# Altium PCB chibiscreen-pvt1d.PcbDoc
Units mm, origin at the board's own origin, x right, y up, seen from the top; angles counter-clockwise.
Board outline 47.28 x 42.63 mm, 2 copper layers (Top Layer, Bottom Layer), stack 1.571 mm thick; 38 components, 30 nets, 404 pads, 49 vias.
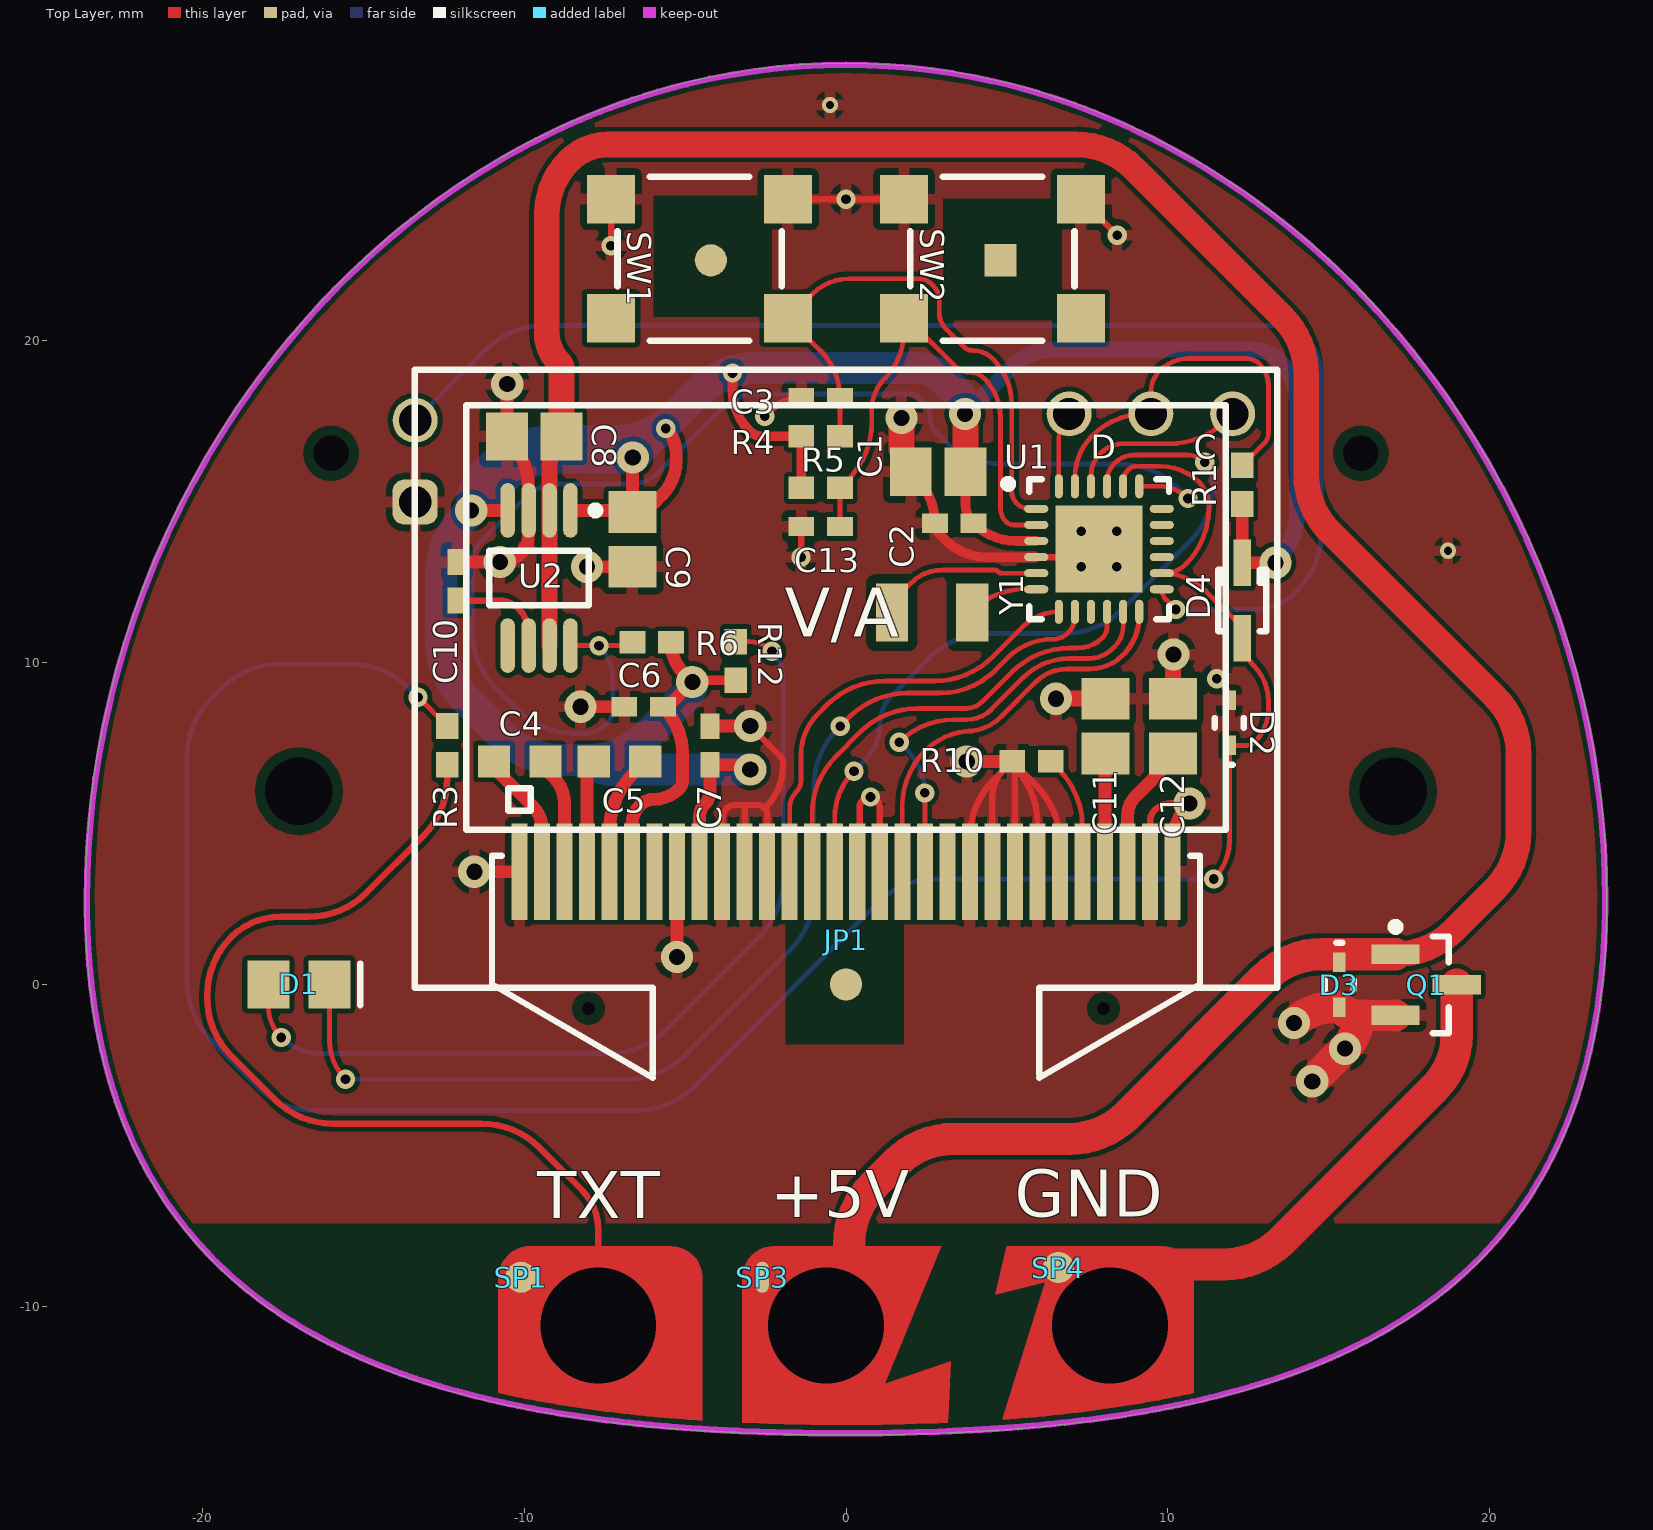
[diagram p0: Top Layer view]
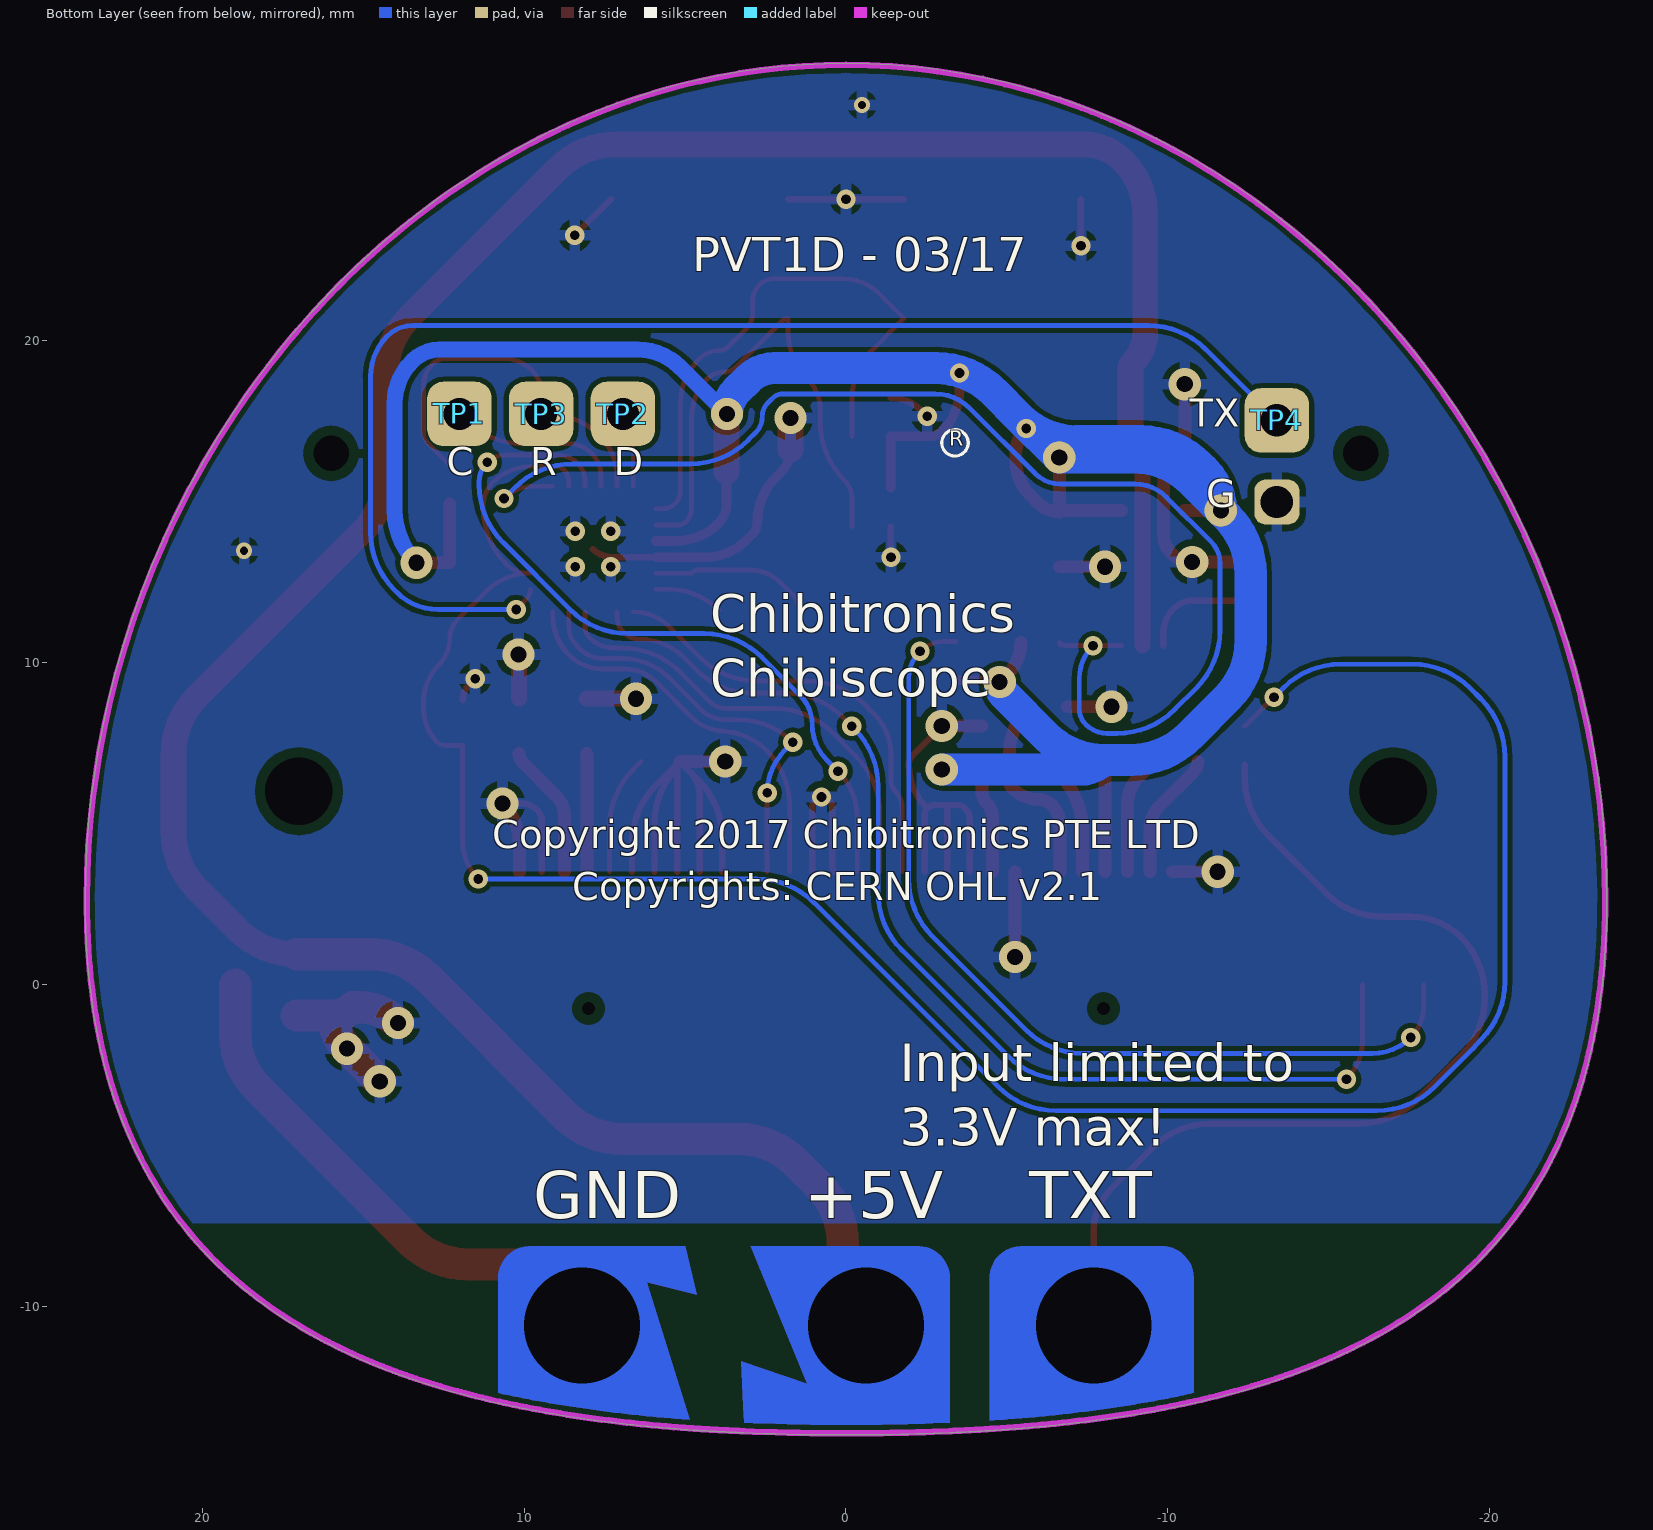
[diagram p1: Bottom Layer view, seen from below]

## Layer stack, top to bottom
Top Solder: solder mask 0.0102, Solder Resist, Dk 3.5
Top Layer: signal copper 0.0356
Dielectric 1: dielectric 1.5, FR-4, Dk 4.8
Bottom Layer: signal copper 0.0356
Bottom Solder: solder mask 0.0102, Solder Resist, Dk 3.5

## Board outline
1747 vertices, not listed, extent -23.641,-14 23.641,28.625

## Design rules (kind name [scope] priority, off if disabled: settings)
Clearance Clearance_NPTH [PadIsPlated = 'False'] p1: gap=0.3 ignorepadtopadclearanceinfootprint=FALSE except(0: Arc-Hole Track-Hole SMDPad-Hole THPad-Hole Via-Hole Fill-Hole Poly-Hole Region-Hole Text-Hole)
Clearance [All] p2: gap=0.15 ignorepadtopadclearanceinfootprint=FALSE except(0: Arc-Hole Track-Hole SMDPad-Hole THPad-Hole Via-Hole Fill-Hole Poly-Hole Region-Hole Text-Hole)
ComponentClearance [All] p1 off: gap=0.254 collisioncheckmode=3 verticalgap=0.254 showdistances=FALSE
HoleSize [All] p1: absolutevalues=TRUE maxlimit=4 minlimit=0.025 maxpercent=80.000 minpercent=20.000
MinimumSolderMaskSliver [All] p1 off: minsoldermaskwidth=0.254
NetAntennae [All] p1 off: netantennaetolerance=0
PlaneConnect [All] p1: planeconnectstyle=Relief reliefexpansion=0.4 reliefentries=4 reliefconductorwidth=0.35 reliefairgap=0.2
PolygonConnect [All] p1: connectstyle=Relief reliefconductorwidth=0.35 reliefentries=4 polygonreliefangle="90 Angle" airgapwidth=0.2
RoomDefinition 01oled [InComponentClass('01oled')] p1 off: confinementstyle=ConfineIn formatcopy=TRUE lockcomponents=FALSE outline 70.294,-25.539 62.928,-25.539 62.928,-29.476 70.294,-29.476
RoutingVias [All] p1: holewidth=0.3 width=0.6 viastyle="Through Hole" minholewidth=0.3 minwidth=0.6 maxholewidth=0.8 maxwidth=1.2
SilkToSilkClearance [All] p1 off: silktosilkclearance=0.254
SilkToSolderMaskClearance [IsPad] p1 off: minsilkscreentomaskgap=0.254 clearancetoexposedcopper=TRUE
SolderMaskExpansion [All] p1: expansion=0.08
Width [All] p1: maxlimit=1 minlimit=0.15 preferedwidth=0.2
23 further rules are at their usual default settings.

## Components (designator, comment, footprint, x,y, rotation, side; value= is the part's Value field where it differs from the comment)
C1 "10uF, 10V, X5R" CAPC2012N 2.863,15.928 r180 top
C2 "0.1uF, 10V, X5R" CAPC1005N 3.363,14.328 r180 top
C3 "0.01uF, 10V, X7R" CAPC1005N -0.787,18.228 r180 top
C4 "1.0uF, 25V, X5R" CAPC1608N -10.137,6.928 r180 top
C5 "1.0uF, 25V, X5R" CAPC1608N -7.037,6.928 r180 top
C6 "1.0uF, 10V, X5R" CAPC1005N -6.287,8.628 r180 top
C7 "1.0uF, 10V, X5R" CAPC1005N -4.225,7.425 r90 top
C8 "10uF, 10V, X5R" CAPC2012N -9.687,17.028 r180 top
C9 "10uF, 10V, X5R" CAPC2012N -6.637,13.828 r270 top
C10 "0.033uF, 16V, X7R" CAPC1005N -12.087,12.528 r270 top
C11 "4.7uF, 25V, X7R" CAPC2012N 8.063,8.028 r90 top
C12 "4.7uF, 25V, X7R" CAPC2012N 10.163,8.028 r90 top
C13 "0.01uF, 10V, X7R" CAPC1005N -0.787,14.228 r180 top
D1 "white LED 0805" CD2012-0805 -17,0 r0 top
D2 "ESD5Z3.3T1" SOD-523 11.913,8.128 r90 top
D3 "ESD5Z5.0T1G" SOD-523 15.328,-0.013 r270 top
D4 "NSR0530HT1G" SOD-323 12.313,11.928 r90 top
JP1 "ER-OLED0.96-3W" ER-OLED0.96-FOLD 0,4 r0 top locked
Q1 "AO3414" SOT23-3N 18.028,-0.013 r0 top
R1 "10k, 1%" RESC1005N 12.313,15.528 r90 top
R3 "330, 1%" RESC1005N -12.387,7.428 r90 top
R4 "1k, 1%" RESC1005N -0.787,17.028 r0 top
R5 "1k, 1%" RESC1005N -0.787,15.428 r0 top
R6 "10k, 1%" RESC1005N -6.037,10.628 r180 top
R10 "390k, 1%" RESC1005N 5.763,6.928 r180 top
R12 "330, 1%" RESC1005N -3.425,10.05 r90 top
SP1 "sticker pad (DNP)" TP_SMT_38mil#1 -10.1,-9.1 r90 top
SP3 "sticker pad (DNP)" TP_SMT_38mil#2 -2.6,-9.1 r90 top
SP4 "sticker pad (DNP)" TP_SMT_38mil#1 6.6,-8.8 r90 top
SW1 "5x5mm 1.6mm tall PB" SWITCH_TS-1187A -1.8,24.4 r270 top
SW2 "5x5mm 1.6mm tall PB" SWITCH_TS-1187A 7.3,24.4 r270 top
TP1 "test point (DNP)" TP_2MM_SQ 12.013,17.728 r180 bottom
TP2 "test point (DNP)" TP_2MM_SQ 6.933,17.728 r180 bottom
TP3 "test point (DNP)" TP_2MM_SQ 9.473,17.728 r180 bottom
TP4 "test point (DNP)" TP_2MM_SQ -13.387,17.528 r180 bottom
U1 "MKL02Z32VFK4" QFN50P400X400X100_HS-25N 7.863,13.528 r0 top
U2 "LP3982IMM-3.3/NOPB" MUA08A_N -9.537,12.628 r270 top
Y1 "32.768kHz" ABS07-120 2.675,11.55 r0 top

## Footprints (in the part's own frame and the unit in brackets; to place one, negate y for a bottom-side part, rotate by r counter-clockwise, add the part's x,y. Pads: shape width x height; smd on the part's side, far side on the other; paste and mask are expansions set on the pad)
ABS07-120 [mm] "32.768kHz SMD low-ESR"
  rect 1x1.8 smd: 1(-1.25,0) 2(1.25,0)
  body extent -1.6,-0.75 1.6,0.75, height 0.9
CAPC1005N [mm] "Chip Capacitor, Body 1.0x0.5mm, IPC Medium Density"
  rect 0.8x0.6 smd: 1(-0.6,0) 2(0.6,0)
  body extent -0.55,-0.3 0.55,0.3, height 0.6
CAPC1608N [mm] "Chip Capacitor, Body 1.6x0.8mm, IPC Medium Density"
  rect 1x1 smd: 1(-0.8,0) 2(0.8,0)
  body extent -0.88,-0.48 0.87,0.48, height 0.85
CAPC2012N [mm] "Chip Capacitor, Body 2.0x1.3mm, IPC Medium Density"
  rect 1.3x1.5 smd: 1(-0.85,0) 2(0.85,0)
  body extent -1.1,-0.72 1.1,0.73, height 1.1
CD2012-0805 [mm] "Chip Diode; Body 2.0 x 1.3 mm (LxW typ)"
  rect 1.3x1.5 smd: 1(-0.95,0) 2(0.95,0)
  silkscreen extent 1.9,-0.65 1.9,0.65
ER-OLED0.96-FOLD [mm] "ER-OLED 0.96in Direct to PCB mount, folded"
  round 0.2 hole 0.4 unplated mask+0.3: 0(8,-4.75) 1(-8,-4.75)
  rect 0.5x3 smd mask+0.07: 1(-10.15,-0.5) 2(-9.45,-0.5) 3(-8.75,-0.5) 4(-8.05,-0.5) 5(-7.35,-0.5) 6(-6.65,-0.5) 7(-5.95,-0.5) 8(-5.25,-0.5) 9(-4.55,-0.5) 10(-3.85,-0.5) 11(-3.15,-0.5) 12(-2.45,-0.5) 13(-1.75,-0.5) 14(-1.05,-0.5) 15(-0.35,-0.5) 16(0.35,-0.5) 17(1.05,-0.5) 18(1.75,-0.5) 19(2.45,-0.5) 20(3.15,-0.5) 21(3.85,-0.5) 22(4.55,-0.5) 23(5.25,-0.5) 24(5.95,-0.5) 25(6.65,-0.5) 26(7.35,-0.5) 27(8.05,-0.5) 28(8.75,-0.5) 29(9.45,-0.5) 30(10.15,-0.5)
  silkscreen extent -13.4,-6.9 13.4,15.1, body extent -13.4,-4.1 13.4,15.1, height 1.61
MUA08A_N [mm] "TSOP, 8-Leads, Body 3x3mm, Pitch 0.65mm, IPC Medium Density"
  oval 1.7x0.45 smd: 1(-2.1,0.975) 2(-2.1,0.325) 3(-2.1,-0.325) 4(-2.1,-0.975) 5(2.1,-0.975) 6(2.1,-0.325) 7(2.1,0.325) 8(2.1,0.975)
  silkscreen extent -2.22,-1.55 0.85,1.88, body extent -1.55,-1.55 1.55,1.55, height 1.09
QFN50P400X400X100_HS-25N [mm] "QFN, 24-Leads, Body 4.00x4.00mm, Pitch 0.50mm, Thermal Pad 2.80x2.80mm, IPC Medium Density"
  oval 0.75x0.25 smd mask+0.07: 1(-1.95,1.25) 2(-1.95,0.75) 3(-1.95,0.25) 4(-1.95,-0.25) 5(-1.95,-0.75) 6(-1.95,-1.25) 13(1.95,-1.25) 14(1.95,-0.75) 15(1.95,-0.25) 16(1.95,0.25) 17(1.95,0.75) 18(1.95,1.25)
  oval 0.25x0.75 smd mask+0.07: 7(-1.25,-1.95) 8(-0.75,-1.95) 9(-0.25,-1.95) 10(0.25,-1.95) 11(0.75,-1.95) 12(1.25,-1.95) 19(1.25,1.95) 20(0.75,1.95) 21(0.25,1.95) 22(-0.25,1.95) 23(-0.75,1.95) 24(-1.25,1.95)
  rect 2.7x2.7 smd mask+0: 25(0,0)
  silkscreen extent -2.95,-2.17 2.18,2.18, body extent -2.03,-2.03 2.03,2.03, height 1
RESC1005N [mm] "Chip Resistor, Body 1.1x0.5mm, IPC Medium Density"
  rect 0.8x0.7 smd: 1(-0.6,0) 2(0.6,0)
  body extent -0.55,-0.3 0.55,0.3, height 0.4
SOD-323 [mm] "SOD-323/SC-76; 2 Leads; Body 1.7 x 1.3 mm, (LxW)"
  rect 1.45x0.55 smd: 1(1.175,0) 2(-1.175,0)
  silkscreen extent -0.95,-0.75 0.95,0.75
SOD-523 [mm] "Molded Diode, 2-Leads, Body 1.2x0.8mm, IPC Medium Density"
  rect 0.6x0.4 smd: 1(-0.7,0) 2(0.7,0)
  silkscreen extent -1.3,-0.45 0.15,0.45, body extent -0.65,-0.45 0.65,0.45, height 0.7
SOT23-3N [mm] "SOT23, 3-Leads, Body 2.9x1.3mm, Pitch 0.95mm, Lead Span 2.5mm, IPC Medium Density"
  rect 1.5x0.6 smd: 1(-0.95,0.95) 2(-0.95,-0.95) 3(0.95,0)
  silkscreen extent -1.07,-1.5 0.7,1.92, body extent -0.7,-1.5 0.7,1.5, height 1.1
SWITCH_TS-1187A [mm] "TS-1187A tact switch, Chi Fung Electronics"
  rect 1.5x1.5 smd mask+0.07: 1(0,0) 2(0,-5.5) 3(3.7,0) 4(3.7,-5.5)
  silkscreen extent -0.7,-5.3 4.4,-0.2, body extent -0.7,-5.3 4.4,-0.2, height 1.6
TP_2MM_SQ [mm] "2mm x 2mm square test pad"
  rrect50% 2x2 smd: 1(0,0)
TP_SMT_38mil#1 [mil] "38 mil round test point, SMT"
  round 38 smd: 1(0,0)
TP_SMT_38mil#2 [mil] "38 mil round test point, SMT"
  oval 38x15.75 smd: 1(0,0)

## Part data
C1 C8 C9: library part "Cap Semi", "Capacitor (Semiconductor SIM Model)", MPN=CL21A106KPCLQNC
C2: library part "Cap Semi", "Capacitor (Semiconductor SIM Model)", MPN=CL05A104KP5NNNC
C3 C13: library part "Cap Semi", "Capacitor (Semiconductor SIM Model)", MPN=CL05B103KP5NNNC
C4 C5: library part "Cap Semi", "Capacitor (Semiconductor SIM Model)", MPN=CL10A105KA8NNNC
C6 C7: library part "Cap Semi", "Capacitor (Semiconductor SIM Model)", MPN=CL05A105KP5NNND
C10: library part "Cap Semi", "Capacitor (Semiconductor SIM Model)", MPN=CL05B333KO5NNNC
C11 C12: library part "Cap Semi", "Capacitor (Semiconductor SIM Model)", MPN=CL21B475KAFNNNE
D1: library part LED2, "White LED", MPN=CB-2012QWC-P8
D2: library part Tranzorb, "On Semi 3.3V standoff TVS diode", MPN=ESD5Z3.3T1G
D3: library part Tranzorb, "On Semi 5.0V standoff TVS diode"
D4: library part "D Schottky", "Schottky Diode", MPN=NSR0530H-D
JP1: "0.96in OLED, 128x64, white"
Q1: library part MOSFET-N, "N-Channel MOSFET"
R1 R6: library part Res1, "Resistor", MPN=RS02U103FT
R3: library part Res1, "Resistor", MPN=RS02U101FT
R4 R5: library part Res1, "Resistor", MPN=RS02U102FT
R10: library part Res1, "Resistor", MPN=RS02U394FT
R12: library part Res1, "Resistor", MPN=RS02U331FT
SP1 SP3 SP4 TP1 TP2 TP3 TP4: library part CON1, "Connector"
SW1 SW2: library part "Header 4", "Chi Fung TS-1187A", MPN=SW-PB-5X5-1.6
U1: "Kinetis KL02 32 KB Flash, 48MHz Cortex-M0+"
U2: "Micropower, Ultra Low-Dropout, Low-Noise, 300mA CMOS Regulator, 8-pin Mini SOIC, Pb-Free", Manufacturer="National Semiconductor", PackageTopMarking=ZXTT*LEUB, PowerWise=N
Y1: library part XTAL, "3.2 x 1.5mm 32.768 kHz crystal, 6pF CL 70k ESR, 20ppm", MPN=SJFC1332K06F20

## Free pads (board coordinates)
  round 2 hole 2.1 unplated: 0(-17,6) 0(17,6)
  round 0.7 hole 1.1 unplated: 0(-16,16.5) 0(16,16.5)
  round 1.8 hole 3.6 mask+0.07: 0(-7.7,-10.6) 0(-0.625,-10.6) 0(8.2,-10.6)
  rect 0.254x0.051 on Bottom Overlay: 1(-2.553,13.231) 1(-2.553,13.282) 1(-2.553,13.333) 1(-2.553,13.383) 1(-2.553,13.434) 1(-2.553,13.485) 1(-2.553,13.536) 1(-2.553,13.587) 1(-2.553,13.637) 1(-2.553,13.688) 1(-2.553,13.739) 1(-2.553,13.79) 1(-2.553,13.841) 1(-2.553,13.891) 1(-2.553,13.993) 1(-2.553,14.044) 1(-2.553,14.095) 1(-2.553,14.145) 1(-2.553,14.196) 1(-2.553,14.247) 1(-2.553,14.349) 1(-2.553,14.399) 1(-2.553,14.45) 1(-2.553,14.501) 1(-2.553,14.552) 1(-2.553,14.603) 1(-2.553,14.653) 1(-2.553,14.755) 1(-2.553,14.806) 1(-2.553,14.857) 1(-2.553,14.907) 1(-2.553,14.958) 1(-2.553,15.009) 1(-2.553,15.111) 1(-2.553,15.161) 1(-2.553,15.212) 1(-2.553,15.263) 1(-2.553,15.314) 1(-2.553,15.365) 1(-2.553,15.466) 1(-2.553,15.517) 1(-2.553,15.568) 1(-2.553,15.619) 1(-2.553,15.669) 1(-2.553,13.18) 1(-2.553,13.942) 1(-2.553,14.298) 1(-2.553,14.704) 1(-2.553,15.06) 1(-2.553,15.415) 1(-2.502,12.977) 1(-2.502,13.028) 1(-2.502,15.822) 1(-2.451,15.974) 1(-0.724,13.079) 1(0.749,13.079) 1(2.426,16.025) 1(2.476,15.923) 1(2.476,12.926) 1(2.527,13.079) 1(2.527,13.129) 1(2.527,15.72) 1(2.527,15.771) 1(2.578,13.282) 1(2.578,13.333) 1(2.578,13.383) 1(2.578,13.434) 1(2.578,13.485) 1(2.578,13.536) 1(2.578,13.587) 1(2.578,13.637) 1(2.578,13.688) 1(2.578,13.739) 1(2.578,13.79) 1(2.578,13.841) 1(2.578,13.891) 1(2.578,13.942) 1(2.578,13.993) 1(2.578,14.044) 1(2.578,14.095) 1(2.578,14.145) 1(2.578,14.196) 1(2.578,14.247) 1(2.578,14.298) 1(2.578,14.349) 1(2.578,14.399) 1(2.578,14.45) 1(2.578,14.501) 1(2.578,14.552) 1(2.578,14.603) 1(2.578,14.653) 1(2.578,14.704) 1(2.578,14.755) 1(2.578,14.806) 1(2.578,14.857) 1(2.578,14.907) 1(2.578,14.958) 1(2.578,15.009) 1(2.578,15.06) 1(2.578,15.111) 1(2.578,15.161) 1(2.578,15.212) 1(2.578,15.263) 1(2.578,15.314) 1(2.578,15.365) 1(2.578,15.415) 1(2.578,15.466) 1(2.578,15.517)
  rect 0.305x0.051 on Bottom Overlay: 1(-2.527,13.079) 1(-2.527,13.129) 1(-2.527,15.72) 1(-2.527,15.771) 1(-2.477,12.875) 1(-2.477,12.926) 1(-2.477,15.873) 1(-2.477,15.923) 1(-2.426,12.774) 1(-2.426,12.825) 1(-2.426,16.025) 1(-2.426,16.076) 1(-2.375,12.672) 1(-2.375,12.723) 1(-2.375,16.127) 1(-2.324,12.621) 1(-2.324,16.228) 1(-2.273,12.52) 1(-2.273,16.279) 1(-2.223,12.469) 1(-0.749,13.028) 1(-0.699,12.926) 1(-0.699,12.977) 1(0.013,12.977) 1(0.013,13.028) 1(0.013,13.079) 1(0.724,12.977) 1(0.724,13.028) 1(1.283,13.637) 1(1.283,13.688) 1(1.283,14.399) 1(1.283,14.45) 1(1.283,13.485) 1(1.283,13.536) 1(1.283,13.587) 1(1.283,13.739) 1(1.283,13.79) 1(1.283,13.841) 1(1.283,13.891) 1(1.283,14.247) 1(1.283,14.298) 1(1.283,14.349) 1(1.283,14.501) 1(1.283,14.552) 1(1.283,14.603) 1(1.283,14.653) 1(2.248,16.33) 1(2.299,12.571) 1(2.299,16.279) 1(2.349,12.621) 1(2.349,12.672) 1(2.349,16.177) 1(2.4,12.723) 1(2.4,12.774) 1(2.4,16.076) 1(2.4,16.127) 1(2.451,15.974) 1(2.451,12.825) 1(2.451,12.875) 1(2.502,15.822) 1(2.502,12.977) 1(2.502,13.028) 1(2.502,15.873) 1(2.553,13.18) 1(2.553,13.231) 1(2.553,15.568) 1(2.553,15.619) 1(2.553,15.669)
  rect 0.356x0.051 on Bottom Overlay: 1(-2.35,16.177) 1(-2.299,12.571) 1(-2.248,16.33) 1(-2.197,16.381) 1(-2.197,12.418) 1(-2.146,12.367) 1(-2.146,16.431) 1(-2.096,12.317) 1(0.648,12.875) 1(0.698,12.926) 1(2.07,16.533) 1(2.121,12.367) 1(2.121,16.482) 1(2.172,12.418) 1(2.172,16.431) 1(2.222,12.469) 1(2.222,16.381) 1(2.273,12.52) 1(2.324,16.228)
  rect 0.406x0.051 on Bottom Overlay: 1(-2.121,16.482) 1(-2.07,16.533) 1(-2.019,16.584) 1(-2.019,12.266) 1(-1.969,12.215) 1(-0.648,12.875) 1(0.013,12.926) 1(1.943,16.635) 1(1.994,16.584) 1(2.045,12.266) 1(2.095,12.317)
  rect 0.457x0.051 on Bottom Overlay: 1(-1.943,16.635) 1(-1.892,12.164) 1(-0.368,12.621) 1(1.867,16.685) 1(1.918,12.164) 1(1.968,12.215)
  rect 0.508x0.051 on Bottom Overlay: 1(-1.867,16.685) 1(-1.816,12.113) 1(-1.765,16.736) 1(0.013,12.875) 1(0.368,12.621) 1(1.791,16.736) 1(1.841,12.113)
  rect 0.559x0.051 on Bottom Overlay: 1(-1.74,12.063) 1(1.714,12.063)
  rect 0.61x0.051 on Bottom Overlay: 1(-1.664,16.787) 1(0.368,12.672) 1(1.689,16.787)
  rect 0.66x0.051 on Bottom Overlay: 1(-1.588,12.012) 1(-0.368,12.672) 1(1.613,12.012)
  rect 0.762x0.051 on Bottom Overlay: 1(-1.537,16.838) 1(1.511,16.838)
  rect 1.27x0.051 on Bottom Overlay: 1(-1.283,13.942) 1(-1.283,13.993) 1(-1.283,14.095) 1(-1.283,14.196) 1(-1.283,14.044) 1(-1.283,14.145) 1(1.308,14.044) 1(1.308,14.095) 1(1.308,14.145) 1(1.308,13.993)
  rect 0.152x0.051 on Bottom Overlay: 1(-0.368,12.571)
  rect 1.473x0.051 on Bottom Overlay: 1(-0.013,12.723)
  rect 1.575x0.051 on Bottom Overlay: 1(-0.013,12.774)
  rect 3.099x0.051 on Bottom Overlay: 1(-0.013,11.809)
  rect 3.708x0.051 on Bottom Overlay: 1(-0.013,11.961)
  rect 3.2x0.051 on Bottom Overlay: 1(-0.013,16.99)
  rect 2.743x0.051 on Bottom Overlay: 1(0.013,11.758)
  rect 3.353x0.051 on Bottom Overlay: 1(0.013,11.859)
  rect 3.556x0.051 on Bottom Overlay: 1(0.013,11.91)
  rect 1.626x0.051 on Bottom Overlay: 1(0.013,12.825)
  rect 3.658x0.051 on Bottom Overlay: 1(0.013,16.889)
  rect 3.454x0.051 on Bottom Overlay: 1(0.013,16.939)
  rect 2.946x0.051 on Bottom Overlay: 1(0.013,17.041)
  rect 2.54x0.051 on Bottom Overlay: 1(0.013,17.092)
  rect 0.203x0.051 on Bottom Overlay: 1(0.368,12.571)
  rect 1.219x0.051 on Bottom Overlay: 1(1.283,13.942) 1(1.283,14.196)
  rrect50% 1.4x1.4 hole 1: 4(-13.387,14.988)
  round 1.4 hole 1: 4(-13.387,17.528) 4(6.933,17.728) 4(9.473,17.728) 4(12.013,17.728)
  round 1 smd mask+1: 6(-4.2,22.5) 6(0,0)
  rect 1x1 smd mask+1: 6(4.8,22.5)

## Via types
v1: diameter 0.6, hole 0.3, Top Layer to Bottom Layer, tented both sides, 22 vias
v2: diameter 1, hole 0.5, Top Layer to Bottom Layer, tented both sides, 21 vias
v3: diameter 0.6, hole 0.3, Top Layer to Bottom Layer, 4 vias
v4: diameter 0.5, hole 0.25, Top Layer to Bottom Layer, tented both sides, 2 vias

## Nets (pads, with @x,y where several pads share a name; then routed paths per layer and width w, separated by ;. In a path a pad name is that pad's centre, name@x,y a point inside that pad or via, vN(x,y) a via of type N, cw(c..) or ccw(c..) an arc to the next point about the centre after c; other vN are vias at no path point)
EXTGND: pad.0@8.2,-10.6 Q1.3 SP4.1 | length 13.5
  Top Layer w1: 10.3,-8.7 11.748,-8.7 ccw(c11.748,-6.16) 13.544,-7.956 18.3,-3.2 ccw(c16.664,-1.564) 18.978,-1.564 Q1.3
GND: C1.2 C2.2 C3.2 C6.2 C7.2 C8.2 C9.2 C10.1 C11.2 C12.2 C13.2 D2.2 D3.2 JP1.1@-10.15,3.5 JP1.8 JP1.10 JP1.11 JP1.12 JP1.16 JP1.17 JP1.21 JP1.22 JP1.23 JP1.24 JP1.25 JP1.29 JP1.30 pad.4@-13.387,14.988 Q1.2 R10.2 SW1.1 SW1.2 SW2.1 SW2.2 U1.4 U1.25 U2.3 | length 83.8
  Top Layer w0.2: v1(-7.3,22.95) SW1.2 ; JP1.10 -3.85,5.113 cw(c-3.338,5.113) -3.7,5.475 cw(c-3.459,5.234) -3.459,5.575 -3.125,5.575 ; JP1.11 -3.15,5.515 cw(c-3.065,5.515) -3.125,5.575 ; v2(-2.975,8.025) -2.074,7.124 cw(c-2.372,6.825) -1.95,6.825 cw(c-3.821,6.825) -2.498,5.502 -2.525,5.475 ; v1(-2.525,17.651) -2.345,17.831 cw(c-1.387,16.874) C3.2 ; JP1.12 -2.45,5.294 ccw(c-2.706,5.294) -2.525,5.475 ; SW1.1 SW2.2 ; v1(-1.4,13.275) ccw(c-1.431,13.306) -1.387,13.306 C13.2 ; JP1.16 ccw(c0.169,3.681) 0.425,3.681 0.425,5.525 cw(c0.666,5.525) 0.496,5.696 0.625,5.825 0.9,5.825 cw(c0.538,5.463) 1.05,5.463 JP1.17 ; JP1.21 3.85,4.563 cw(c6.39,4.563) 4.594,6.359 R10.2 ; JP1.22 4.55,5.851 cw(c5.671,5.851) R10.2@4.878,6.643 ; JP1.23 R10.2@5.25,6.717 ; U1.4 7.259,13.278 ccw(c7.259,14.131) U1.25 ; JP1.24 5.95,5.027 ccw(c3.56,5.027) R10.2@5.25,6.717 ; JP1.25 6.65,4.388 ccw(c4.11,4.388) 5.906,6.184 R10.2 cw(c4.952,6.717) R10.2@5.25,6.717 ; SW2.1 v1(8.425,23.275) ; JP1.29 9.45,5.063 cw(c9.962,5.063) 9.6,5.425 cw(c10.083,4.942) 10.083,5.625 v2(10.675,5.625) ; v1(11.525,9.5) 11.711,9.314 cw(c11.226,8.828) D2.2 ; -3.125,5.575 -2.766,5.575 cw(c-2.766,5.234) -2.525,5.475
  Top Layer w0.3: C1.2@1.725,16.622 ccw(c2.707,16.622) C1.2 2.162,15.779 cw(c0.711,14.328) C2.2 ccw(c3.222,14.328) 2.897,14.003 3.1,13.8 ccw(c4.361,15.061) 4.361,13.278 U1.4 ; v2(1.725,17.6) 1.95,17.6 2.025,17.675 ccw(c2.055,17.645) v2@2.013,17.645
  Top Layer w0.4: C10.1 v2(-10.757,13.128) ccw(c-10.757,14.057) -10.1,13.4 ccw(c-10.674,13.974) -9.862,13.974 U2.3 -9.862,15.398 ccw(c-12.167,15.398) C8.2 -10.537,18.62 cw(c-10.495,18.62) v2(-10.525,18.65) ; v2(-11.55,3.5) JP1.1@-10.15,3.5 ; v2(-8.247,8.628) C6.2 ; v2(-8.047,12.978) C9.2 ; v2(-5.25,0.85) JP1.8 ; C7.2 v2(-2.975,8.025) ; v2(3.753,6.928) R10.2 ; JP1.30 10.15,4.358 cw(c11.942,4.358) v2(10.675,5.625)
  Top Layer w0.5: v2@6.625,8.85 cw(c6.692,8.783) 6.692,8.878 C11.2 ; C12.2 10.163,10.22 cw(c10.205,10.22) v2(10.175,10.25)
  Top Layer w0.8: C1.2@1.725,16.622 v2(1.725,17.6)
  Top Layer w1: v2(13.925,-1.2) cw(c15.102,-2.377) 15.102,-0.713 D3.2 ccw(c15.931,-0.109) 15.931,-0.963 ; v2(14.488,-3.013) v2(15.503,-1.997) ccw(c14.468,-0.963) 15.931,-0.963 ; Q1.2 15.931,-0.963
  other v1: 0.763,5.825 0,24.4
  other v2: 6.525,8.875
  other v3: 7.313,12.978 8.413,12.978 7.313,14.078 8.413,14.078
  other v4: 18.7,13.475 -0.5,27.325
LDO_CC: C10.2 U2.6 | length 3.2
  Top Layer w0.2: C10.2 -10.785,11.928 cw(c-10.785,11.065) -10.175,11.675 cw(c-10.93,10.92) -9.862,10.92 U2.6
MCU_LED: D1.2 U1.8 | length 34.5
  Top Layer w0.15: D1.2 -16.05,-1.743 ccw(c-14.343,-1.743) v1(-15.55,-2.95) ; v1(-0.175,8.025) 0.106,8.306 cw(c1.902,6.51) 1.902,9.05 2.925,9.05 ccw(c2.925,11.464) 4.632,9.757 5.022,10.147 cw(c6.417,8.752) 6.417,10.725 ccw(c6.417,11.408) 6.9,10.925 ccw(c6.387,11.438) 7.113,11.438 U1.8
  Bottom Layer w0.15: v1(-15.55,-2.95) -6.802,-2.95 ccw(c-6.802,-0.41) -5.006,-2.206 -1.744,1.056 ccw(c-3.54,2.852) -1,2.852 -1,6.148 cw(c1.54,6.148) -0.256,7.944 v1(-0.175,8.025)
MODE_PB: C3.1 R4.2 SW1.3 U1.1 | length 17.8
  Top Layer w0.15: R4.2 C3.1 ccw(c-2.262,18.228) -0.795,19.695 SW1.3 -1.052,21.448 cw(c0.1,20.295) 0.1,21.925 2.253,21.925 cw(c2.253,21.328) 2.675,21.75 2.706,21.719 cw(c2.236,21.25) 2.9,21.25 2.9,20.858 ccw(c3.583,20.858) 3.1,20.375 3.669,19.806 ccw(c3.925,20.062) 3.925,19.7 cw(c3.925,18.795) 4.565,19.435 cw(c3.153,18.023) 5.15,18.023 5.15,15.312 ccw(c5.662,15.312) 5.3,14.95 ccw(c5.716,15.366) 5.716,14.778 U1.1
NetD1_1: D1.1 R12.2 | length 28.5
  Top Layer w0.15: D1.1 -17.95,-0.684 ccw(c-16.584,-0.684) v1(-17.55,-1.65) ; R12.2 -3.024,10.65 cw(c-3.024,9.626) v1(-2.3,10.35)
  Bottom Layer w0.15: v1(-17.55,-1.65) ccw(c-16.343,-0.443) -16.343,-2.15 -7.377,-2.15 ccw(c-7.377,0.39) -5.581,-1.406 -2.694,1.481 ccw(c-4.49,3.277) -1.95,3.277 -1.95,9.505 ccw(c-3.145,9.505) v1(-2.3,10.35)
NetU1_5: U1.5 Y1.1 | length 5.2
  Top Layer w0.15: Y1.1 cw(c2.21,11.55) 1.655,12.105 2.025,12.475 cw(c2.991,11.509) 2.991,12.875 4.604,12.875 cw(c4.604,12.704) 4.725,12.825 ccw(c4.839,12.939) 4.839,12.778 U1.5
NetU1_6: U1.6 Y1.2 | length 2.1
  Top Layer w0.15: Y1.2@3.95,11.625 cw(c5.526,10.049) 5.526,12.278 U1.6
OLED_C1N: C5.1 JP1.5 | length 3.8
  Top Layer w0.4: JP1.5 -7.35,4.763 cw(c-4.81,4.763) -6.606,6.559 C5.1
OLED_C1P: C5.2 JP1.4 | length 3.5
  Top Layer w0.4: JP1.4 -8.05,6.414 cw(c-7.324,6.414) C5.2
OLED_C2N: C4.1 JP1.3 | length 3.6
  Top Layer w0.4: C4.1 ccw(c-8.757,6.928) C4.1@-9.168,6.518 ; C4.1@-9.167,6.517 -9.075,6.425 cw(c-9.86,5.64) -8.75,5.64 JP1.3
OLED_C2P: C4.2 JP1.2 | length 4
  Top Layer w0.4: C4.2 ccw(c-10.478,6.928) -10.803,6.603 -9.725,5.525 cw(c-10.389,4.861) -9.45,4.861 JP1.2
OLED_CS: JP1.13 U1.7 | length 13.7
  Top Layer w0.15: JP1.13 -1.75,5.492 cw(c-1.067,5.492) -1.55,5.975 ccw(c-1.912,6.337) -1.4,6.337 -1.4,7.133 cw(c0.392,7.133) -0.875,8.4 -0.594,8.681 cw(c1.202,6.885) 1.202,9.425 2.748,9.425 ccw(c2.748,11.965) 4.544,10.169 5.486,11.111 cw(c6.613,9.985) U1.7
OLED_DC: JP1.15 U1.21 | length 23.5
  Top Layer w0.15: JP1.15 -0.35,5.176 cw(c1.699,5.176) v1(0.25,6.625) ; U1.21 8.113,15.641 cw(c8.892,15.641) 8.341,16.192 cw(c8.964,15.569) 8.964,16.45 10.607,16.45 cw(c10.607,15.682) v1(11.15,16.225)
  Bottom Layer w0.15: v1(0.25,6.625) 0.59,6.965 ccw(c-0.519,8.075) 1.05,8.075 cw(c2.317,8.075) 1.421,8.971 2.606,10.156 cw(c4.402,8.36) 4.402,10.9 6.773,10.9 ccw(c6.773,13.44) 8.569,11.644 10.656,13.731 ccw(c8.86,15.527) 11.4,15.527 11.4,15.621 ccw(c10.546,15.621) v1(11.15,16.225)
OLED_IREF: JP1.26 R10.1 | length 3.7
  Top Layer w0.15: R10.1 6.606,6.684 cw(c4.81,4.888) 7.35,4.888 JP1.26
OLED_RES: JP1.14 U1.10 | length 14.1
  Top Layer w0.15: JP1.14 -1.05,5.298 cw(c1.49,5.298) -0.306,7.094 0.431,7.831 cw(c2.227,6.035) 2.227,8.575 3.725,8.575 ccw(c3.725,9.299) 4.237,8.787 5.156,9.706 cw(c6.952,7.91) 6.952,10.45 7.19,10.45 ccw(c7.19,11.56) 7.975,10.775 ccw(c7.643,11.107) 8.113,11.107 U1.10
OLED_VCC: C12.1 JP1.28 | length 4.2
  Top Layer w0.4: JP1.28 8.75,5.246 cw(c9.604,5.246) 9,5.85 C12.1@10.046,6.896 ; C12.1@10.046,6.896 ccw(c9.764,7.178) C12.1
OLED_VCOMH: C11.1 JP1.27 | length 3.7
  Top Layer w0.4: JP1.27 8.05,7.147 cw(c8.093,7.147) C11.1
OPTION_PB: C13.1 R5.2 SW2.4 U1.2 | length 15.8
  Top Layer w0.15: C13.1 -0.187,15.084 cw(c0.644,15.084) 0.056,15.671 ccw(c-1.74,17.467) 0.8,17.467 0.8,17.859 cw(c2.166,17.859) 1.2,18.825 ccw(c-0.249,20.274) 1.8,20.274 SW2.4 cw(c1.8,20.459) 1.971,20.629 3.398,19.202 ccw(c3.825,19.629) 3.825,19.025 cw(c3.825,18.361) 4.294,18.831 cw(c3.074,17.61) 4.8,17.61 4.8,14.797 ccw(c5.397,14.797) 4.975,14.375 ccw(c5.21,14.61) 5.21,14.278 U1.2
PWR_FAULT: R6.2 U1.19 U2.8 | length 40.2
  Top Layer w0.15: U2.8 -6.879,10.528 ccw(c-6.879,10.869) R6.2 ccw(c-6.546,10.537) R6.2@-6.675,10.537 ; U1.19 9.713,15.478 cw(c9.713,14.188) v1(10.625,15.1)
  Bottom Layer w0.15: v1(-7.675,10.525) cw(c-8.701,9.499) -7.25,9.499 -7.25,8.558 cw(c-7.933,8.558) -7.45,8.075 cw(c-8.114,8.739) -8.114,7.8 -8.423,7.8 cw(c-8.423,10.34) -10.219,8.544 -10.881,9.206 cw(c-9.085,11.002) -11.625,11.002 -11.625,13.086 cw(c-10.686,13.086) -11.35,13.75 -9.957,15.143 cw(c-8.975,14.162) -8.975,15.55 -6.66,15.55 ccw(c-6.66,16.66) -5.875,15.875 -3.844,17.906 cw(c-2.771,16.833) -2.771,18.35 1.938,18.35 cw(c1.938,17.838) 2.3,18.2 2.423,18.077 cw(c1.996,17.65) 2.6,17.65 ccw(c3.324,17.65) 2.812,17.138 3.031,16.919 ccw(c4.827,18.715) 4.827,16.175 8.498,16.175 cw(c8.498,13.635) 10.294,15.431 v1(10.625,15.1)
RESET_N: pad.4@9.473,17.728 R1.2 TP3.1 U1.23 | length 11.9
  Top Layer w0.15: U1.23 7.113,15.753 cw(c8.947,15.753) 7.65,17.05 cw(c9.286,15.414) 9.286,17.728 9.473,17.728 9.473,18.405 cw(c10.42,18.405) 9.75,19.075 cw(c10.655,18.17) 10.655,19.45 12.428,19.45 cw(c12.428,18.853) 12.85,19.275 cw(c12.186,18.611) 13.125,18.611 13.125,17.125 cw(c12.679,17.125) 12.994,16.809 R1.2
RX_EXT: pad.0@-7.7,-10.6 R3.1 SP1.1 | length 30.3
  Top Layer w0.2: R3.1 -12.387,6.415 cw(c-14.927,6.415) -13.131,4.619 -14.906,2.844 cw(c-16.702,4.64) -16.702,2.1 -17.583,2.1 ccw(c-17.583,-0.055) -19.106,1.469 ccw(c-17.31,-0.327) -19.85,-0.327 -19.85,-0.423 ccw(c-17.31,-0.423) -19.106,-2.219 -17.744,-3.581 ccw(c-15.948,-1.785) -15.948,-4.325 -11.327,-4.325 cw(c-11.327,-6.865) -9.531,-5.069 -8.2,-6.4 cw(c-9.407,-7.607) -7.7,-7.607 pad.0@-7.7,-10.6
SPI1_MOSI: JP1.19 U1.11 | length 13.1
  Top Layer w0.15: v1(1.65,7.525) cw(c3.34,5.835) 3.34,8.225 3.75,8.225 ccw(c3.75,9.311) 4.518,8.543 5.512,9.537 ; JP1.19 v1(2.45,5.95) ; 5.513,9.538 cw(c6.93,8.12) 6.93,10.125 7.55,10.125 ccw(c7.55,11.15) 8.275,10.425 8.35,10.5 ccw(c7.716,11.134) 8.613,11.134 U1.11
  Bottom Layer w0.15: v1(1.65,7.525) 1.902,7.273 cw(c0.579,5.95) v1(2.45,5.95)
SPI1_SCK: JP1.18 U1.12 | length 14.1
  Top Layer w0.15: JP1.18 1.75,5.551 cw(c4.161,5.551) 2.456,7.256 cw(c3.95,5.763) 3.749,7.865 ; U1.12 U1.12@9.113,11.489 ; 3.749,7.865 cw(c3.95,5.763) 3.915,7.875 ; 3.749,7.865 ccw(c3.749,9.355) 3.915,7.875 ; 3.915,7.875 ccw(c3.749,9.355) 4.802,8.302 5.9,9.4 cw(c6.866,8.434) 6.866,9.8 7.579,9.8 ccw(c7.579,11.224) 8.586,10.217 ; 8.586,10.217 ccw(c8.046,10.879) 8.65,10.275 ccw(c7.533,11.392) 9.113,11.392 U1.12@9.113,11.489 ; 8.586,10.217 ccw(c7.315,11.489) U1.12@9.113,11.489
SWD_CLK: pad.4@12.013,17.728 TP1.1 U1.22 | length 5.6
  Top Layer w0.15: U1.22 7.613,15.806 cw(c8.594,15.806) 7.9,16.5 cw(c8.624,15.776) 8.624,16.8 10.033,16.8 ccw(c10.033,19.34) 11.829,17.544 pad.4@12.013,17.728
SWD_DIO: pad.4@6.933,17.728 TP2.1 U1.24 | length 2.3
  Top Layer w0.15: U1.24 6.613,16.955 cw(c7.705,16.955) pad.4@6.933,17.728
UART_RX: D2.1 D4.2 R3.2 U1.14 U1.20 | length 72.7
  Top Layer w0.15: v1(-13.3,8.925) cw(c-13.3,8.888) -13.274,8.914 R3.2 ; U1.20 8.613,15.608 cw(c9.167,15.608) 8.775,16 cw(c9.016,15.759) 9.016,16.1 9.768,16.1 cw(c9.768,14.393) 10.975,15.6 cw(c10.251,14.876) 11.275,14.876 11.275,14.8 cw(c8.8,14.8) 10.55,13.05 cw(c9.893,13.707) 9.893,12.778 U1.14 cw(c9.813,10.823) 11.195,12.205 12.076,11.324 cw(c11.505,10.753) D4.2 ccw(c13.497,10.753) 12.659,9.916 cw(c11.536,8.792) 13.125,8.792 13.125,8.551 cw(c11.674,8.551) 12.7,7.525 cw(c12.465,7.76) 12.465,7.428 D2.1 11.913,4.452 cw(c10.248,4.452) v1(11.425,3.275)
  Bottom Layer w0.15: v1(-13.3,8.925) -13.581,9.206 ccw(c-15.377,7.41) -15.377,9.95 -17.598,9.95 ccw(c-17.598,7.41) -19.394,9.206 -19.731,8.869 ccw(c-17.935,7.073) -20.475,7.073 -20.475,0.079 ccw(c-17.935,0.079) -19.731,-1.718 -19.685,-1.763 ccw(c-17.685,-0.198) -19.481,-1.994 -18.294,-3.181 ccw(c-16.498,-1.385) -16.498,-3.925 -6.527,-3.925 ccw(c-6.527,-1.385) -4.731,-3.181 0.981,2.531 cw(c2.777,0.735) 2.777,3.275 v1(11.425,3.275)
UART_TX: pad.4@-13.387,17.528 TP4.1 U1.13 | length 41.8
  Top Layer w0.15: U1.13 ccw(c10.272,12.278) 9.947,11.953 v1(10.25,11.65)
  Bottom Layer w0.15: TP4.1 -11.184,19.731 cw(c-9.388,17.935) -9.388,20.475 13.465,20.475 cw(c13.465,19.365) 14.25,20.15 cw(c12.983,18.883) 14.775,18.883 14.775,14.052 cw(c12.235,14.052) 14.031,12.256 13.95,12.175 cw(c12.683,13.442) 12.683,11.65 v1(10.25,11.65)
VBAT_SYS: C8.1 D3.1 pad.0@-0.625,-10.6 Q1.1 SP3.1 U2.2 U2.7 | length 85.5
  Top Layer w0.5: U2.7 -9.212,16.122 cw(c-7.932,16.122) C8.1
  Top Layer w0.8: C8.1 -8.837,19.149 ccw(c-9.051,19.149) -8.9,19.3 cw(c-7.934,20.266) -9.3,20.266 -9.3,23.91 cw(c-6.91,23.91) -8.6,25.6 cw(c-7.393,24.393) -7.393,26.1 7.148,26.1 cw(c7.148,23.56) 8.944,25.356 9.659,24.641 ; 9.659,24.641 13.556,20.744 cw(c11.76,18.948) 14.3,18.948 14.3,15.852 ccw(c16.84,15.852) 15.044,14.056 20.156,8.944 cw(c18.36,7.148) 20.9,7.148 20.9,4.752 cw(c18.36,4.752) 20.156,2.956 18.881,1.681 cw(c17.085,3.477) 17.085,0.937 Q1.1
  Top Layer w1: 0.1,-8.3 0.1,-8.052 cw(c2.64,-8.052) 0.844,-6.256 1.556,-5.544 cw(c3.352,-7.34) 3.352,-4.8 6.948,-4.8 ccw(c6.948,-2.26) 8.744,-4.056 12.993,0.193 cw(c14.789,-1.603) 14.789,0.937 Q1.1
VMCU: C1.1 C2.1 C6.1 C7.1 C9.1 D4.1 JP1.6 JP1.9 R1.1 R4.1 R5.1 R6.1 R12.1 U1.3 U2.1 U2.4 | length 99.6
  Top Layer w0.3: v2(-4.775,9.4) cw(c-4.654,9.279) -4.654,9.45 R12.1 ; v1(-3.525,19) -3.525,18.467 ccw(c-1.733,18.467) -3,17.2 ccw(c-2.584,17.616) -2.584,17.028 R4.1 R5.1 ; v2(3.7,17.725) cw(c3.669,17.694) v2@3.713,17.694 ; C1.1 3.713,14.931 ccw(c4.566,14.931) C2.1 ccw(c5.29,15.656) 5.29,13.778 U1.3
  Top Layer w0.4: v2(-11.647,14.728) U2.4 ; U2.1 -6.758,14.728 cw(c-6.758,14.557) C9.1 ; JP1.6 -6.65,4.971 cw(c-5.796,4.971) -6.4,5.575 cw(c-5.978,5.153) -5.978,5.75 ccw(c-5.978,6.866) -5.188,6.077 ccw(c-5.461,6.35) -5.075,6.35 -5.075,7.149 ccw(c-7.166,7.149) C6.1 ccw(c-5.687,8.966) -5.448,8.727 v2(-4.775,9.4) -5.038,9.663 cw(c-4.072,10.628) R6.1 ; v2(-6.625,16.375) ccw(c-6.595,16.345) -6.637,16.345 C9.1 ; v1(-5.6,17.275) cw(c-6.385,16.49) -5.275,16.49 -5.275,16.275 cw(c-6.784,16.275) -5.717,15.208 -5.971,14.954 cw(c-6.637,15.62) C9.1 ; JP1.9 -4.55,5.203 cw(c-3.953,5.203) -4.375,5.625 ccw(c-4.737,5.987) -4.225,5.987 C7.1 v2@-3.075,6.825 ; R1.1 D4.1 v2(13.347,13.103)
  Top Layer w0.8: C1.1 v2@3.713,17.694
  Bottom Layer w0.5: v2(3.7,17.725) 5.152,19.177 cw(c6.475,17.854) 6.475,19.725 12.63,19.725 cw(c12.63,18.53) 13.475,19.375 cw(c12.147,18.047) 14.025,18.047 14.025,14.739 cw(c11.711,14.739) v2(13.347,13.103)
  Bottom Layer w1: -5.15,17.85 -5.381,17.619 ; v2(-4.775,9.4) cw(c-5.379,9.4) -4.952,8.973 -6.206,7.719 cw(c-8.002,9.515) -8.002,6.975 ; v2(-2.975,6.675) -7.278,6.675 cw(c-7.278,7.699) -8.002,6.975 ; v2(3.7,17.725) ccw(c2.674,17.725) 3.399,18.451 3.05,18.8 ccw(c2.205,17.955) 2.205,19.15 -2.798,19.15 ccw(c-2.798,16.61) -4.594,18.406 -5.381,17.619 ; v2(-11.647,14.728) cw(c-9.897,14.728) -11.135,15.965 -10.969,16.131 cw(c-9.173,14.335) -9.173,16.875 -7.177,16.875 ccw(c-7.177,19.415) -5.381,17.619 ; v2(-11.647,14.728) -11.831,14.544 ccw(c-10.035,12.748) -12.575,12.748 -12.575,10.677 ccw(c-10.035,10.677) -11.831,8.881 -10.669,7.719 ccw(c-8.873,9.515) -8.873,6.975 -8.002,6.975 ; v2(-11.647,14.728) -10.744,15.631 cw(c-8.948,13.835) -8.948,16.375 v2(-6.625,16.375) -5.381,17.619
pads on no net: JP1.0 JP1.1@-8,-0.75 JP1.7 JP1.20 SW1.4 SW2.3 U1.9 U1.15 U1.16 U1.17 U1.18 U2.5

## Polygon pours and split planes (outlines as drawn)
GND on Top Layer "GND_L01_P000" (solid, remove dead copper, pour order 0): -24.8,29.225 19.398,29.225 cw(c19.398,26.685) 21.194,28.481 24.225,25.45 24.225,-14.467 ccw(c24.908,-14.467) 24.425,-14.95 23.519,-15.856 cw(c21.723,-14.06) 21.723,-16.6 -14.1,-16.6 ccw(c-15.488,-16.6) -14.507,-15.618 -27.3,-2.825 -25.269,-0.794 ccw(c-27.065,1.002) -24.525,1.002 -24.525,27.3
GND on Bottom Layer "GND_L02_P002" (solid, remove dead copper, pour order 2): 12.773,30.625 cw(c12.773,28.085) 14.569,29.881 24.956,19.494 cw(c23.16,17.698) 25.7,17.698 25.7,-3.8 13.344,-16.156 cw(c11.548,-14.36) 11.548,-16.9 -16.873,-16.9 cw(c-16.873,-14.36) -18.669,-16.156 -27.55,-7.275 -25.994,-5.719 ccw(c-27.79,-3.923) -25.25,-3.923 -25.25,18.175 -13.544,29.881 cw(c-11.748,28.085) -11.748,30.625

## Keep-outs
Keep-Out Layer:
  lines w0.2: -23.591,2.477 cw(c2.81,2.62) -23.591,2.62 cw(c3.136,2.618) -23.486,4.985 cw(c3.407,2.594) -23.212,7.111 cw(c3.939,2.486) -19.843,16.378 cw(c3.714,2.619) -18.932,17.831 cw(c3.48,2.776) -18.216,18.845 cw(c3.258,2.94) -17.578,19.672 cw(c3.042,3.113) -16.986,20.383 cw(c2.836,3.29) -16.449,20.986 cw(c2.64,3.471) -15.922,21.544 cw(c2.446,3.659) -15.408,22.058 cw(c2.259,3.851) -14.908,22.53 cw(c2.081,4.045) -14.425,22.962 cw(c1.913,4.238) -13.962,23.356 cw(c1.751,4.432) -13.49,23.739 cw(c1.592,4.634) -13.009,24.109 cw(c1.442,4.835) -12.55,24.444 cw(c1.3,5.033) -12.085,24.768 cw(c1.164,5.235) -11.612,25.08 cw(c1.033,5.438) -11.132,25.381 cw(c0.908,5.642) -10.646,25.669 cw(c0.79,5.846) -10.153,25.946 cw(c0.677,6.055) -9.621,26.227 cw(c0.569,6.267) -9.081,26.493 cw(c0.47,6.474) -8.534,26.745 cw(c0.378,6.68) -7.946,26.996 cw(c0.293,6.888) -7.316,27.243 cw(c0.216,7.095) -6.642,27.482 cw(c0.145,7.305) -5.851,27.731 cw(c0.084,7.516) -4.938,27.977 cw(c0,7.888) 0,28.575 cw(c0.001,7.914) 3.976,28.189 cw(c-0.041,7.686) 5.122,27.931 cw(c-0.094,7.478) 5.995,27.688 cw(c-0.156,7.271) 6.749,27.446 cw(c-0.227,7.063) 7.421,27.203 cw(c-0.307,6.853) 8.051,26.953 cw(c-0.394,6.643) 8.637,26.699 cw(c-0.488,6.435) 9.183,26.444 cw(c-0.588,6.227) 9.721,26.175 cw(c-0.695,6.021) 10.219,25.91 cw(c-0.806,5.819) 10.711,25.632 cw(c-0.924,5.615) 11.197,25.342 cw(c-1.05,5.411) 11.675,25.039 cw(c-1.181,5.208) 12.147,24.726 cw(c-1.319,5.006) 12.612,24.4 cw(c-1.461,4.808) 13.069,24.063 cw(c-1.612,4.608) 13.549,23.692 cw(c-1.771,4.408) 14.02,23.308 cw(c-1.933,4.214) 14.483,22.912 cw(c-2.101,4.023) 14.964,22.478 cw(c-2.28,3.83) 15.463,22.004 cw(c-2.466,3.639) 15.976,21.489 cw(c-2.659,3.452) 16.501,20.93 cw(c-2.855,3.273) 17.036,20.325 cw(c-3.059,3.098) 17.626,19.612 cw(c-3.274,2.928) 18.262,18.783 cw(c-3.497,2.763) 18.996,17.734 cw(c-3.959,2.474) 22.654,9.656 cw(c-3.703,2.543) 23.184,7.269 cw(c-3.425,2.592) 23.475,5.107 cw(c-3.143,2.618) 23.591,2.62 23.591,2.534 23.59,2.42 23.589,2.306 23.588,2.192 23.585,2.079 23.583,1.967 23.58,1.855 23.576,1.743 23.572,1.632 23.568,1.522 23.563,1.412 23.557,1.303 23.551,1.194 23.544,1.085 23.537,0.977 23.53,0.87 23.522,0.763 23.514,0.656 23.505,0.55 23.495,0.445 23.485,0.34 23.475,0.235 23.464,0.131 23.453,0.028 23.441,-0.075 23.426,-0.203 23.41,-0.331 23.393,-0.457 23.375,-0.583 23.357,-0.708 23.338,-0.833 23.318,-0.956 23.298,-1.079 23.276,-1.202 23.255,-1.323 23.232,-1.444 23.209,-1.564 23.184,-1.683 23.16,-1.801 23.134,-1.919 23.108,-2.036 23.081,-2.152 23.054,-2.268 23.025,-2.383 22.996,-2.497 22.967,-2.611 22.93,-2.746 22.893,-2.88 22.854,-3.013 22.815,-3.145 22.774,-3.276 22.733,-3.406 22.69,-3.536 22.647,-3.664 22.602,-3.791 22.549,-3.938 22.495,-4.084 22.439,-4.228 22.382,-4.371 22.316,-4.533 22.247,-4.693 22.178,-4.851 22.097,-5.027 22.014,-5.201 21.92,-5.392 21.823,-5.58 cw(c10.477,0.386) 21.713,-5.784 cw(c10.593,0.323) 21.58,-6.021 cw(c10.708,0.256) 21.42,-6.289 cw(c10.82,0.188) 21.211,-6.62 cw(c10.966,0.09) 20.376,-7.748 cw(c10.935,0.117) 19.938,-8.246 cw(c10.838,0.207) 19.674,-8.521 cw(c10.749,0.295) 19.46,-8.732 cw(c10.66,0.387) 19.271,-8.911 cw(c10.571,0.483) 19.093,-9.073 18.927,-9.219 18.774,-9.349 18.634,-9.464 18.493,-9.577 18.35,-9.688 18.221,-9.786 18.092,-9.882 17.96,-9.977 17.844,-10.059 17.728,-10.139 17.61,-10.219 17.491,-10.298 17.371,-10.376 17.25,-10.452 17.146,-10.517 17.041,-10.581 16.935,-10.645 16.829,-10.708 16.722,-10.77 16.614,-10.831 16.505,-10.891 16.396,-10.951 16.286,-11.01 16.176,-11.069 16.064,-11.126 15.953,-11.183 15.84,-11.24 15.746,-11.286 15.651,-11.332 15.556,-11.377 15.46,-11.422 15.364,-11.467 15.267,-11.51 15.17,-11.554 15.073,-11.597 14.975,-11.64 14.877,-11.682 14.778,-11.723 14.679,-11.764 14.579,-11.805 14.479,-11.845 14.378,-11.885 14.277,-11.924 14.176,-11.963 14.074,-12.002 13.972,-12.04 13.869,-12.077 13.766,-12.114 13.663,-12.151 13.559,-12.187 13.454,-12.223 13.35,-12.258 13.245,-12.293 13.139,-12.327 13.033,-12.361 12.927,-12.395 12.82,-12.428 12.713,-12.461 12.605,-12.493 12.497,-12.525 12.389,-12.557 12.28,-12.588 12.171,-12.618 12.062,-12.649 11.952,-12.679 11.842,-12.708 11.731,-12.737 11.62,-12.766 11.509,-12.794 11.397,-12.822 11.285,-12.849 11.172,-12.876 11.059,-12.903 10.946,-12.929 10.81,-12.96 10.759,-12.971 10.657,-12.994 10.555,-13.016 10.453,-13.038 10.35,-13.06 10.247,-13.081 10.144,-13.102 10.04,-13.123 9.936,-13.143 9.832,-13.163 9.728,-13.183 9.624,-13.203 9.519,-13.222 9.414,-13.241 9.308,-13.26 9.203,-13.278 9.097,-13.296 8.991,-13.314 8.884,-13.332 8.778,-13.349 8.671,-13.366 8.564,-13.383 8.456,-13.4 8.348,-13.416 8.241,-13.432 8.132,-13.447 8.024,-13.463 7.915,-13.478 7.806,-13.493 7.697,-13.507 7.588,-13.522 7.478,-13.536 7.368,-13.55 7.258,-13.563 7.148,-13.576 7.037,-13.59 6.926,-13.602 6.815,-13.615 6.704,-13.627 6.593,-13.639 6.481,-13.651 6.369,-13.662 6.257,-13.674 6.144,-13.684 6.031,-13.695 5.919,-13.706 5.805,-13.716 5.692,-13.726 5.579,-13.736 5.465,-13.745 5.351,-13.755 5.237,-13.764 5.122,-13.772 5.007,-13.781 4.893,-13.789 4.771,-13.798 4.766,-13.798 4.739,-13.8 4.714,-13.802 4.688,-13.803 4.663,-13.805 4.637,-13.807 4.611,-13.808 4.586,-13.81 4.56,-13.812 4.535,-13.813 4.509,-13.815 4.485,-13.817 4.461,-13.818 4.437,-13.82 4.413,-13.821 4.389,-13.823 4.365,-13.824 4.341,-13.825 4.316,-13.827 4.292,-13.828 4.268,-13.83 4.246,-13.831 4.223,-13.832 4.201,-13.834 4.178,-13.835 4.155,-13.836 4.133,-13.837 4.11,-13.839 4.088,-13.84 4.065,-13.841 4.043,-13.842 4.022,-13.843 4.001,-13.845 3.98,-13.846 3.959,-13.847 3.938,-13.848 3.916,-13.849 3.895,-13.85 3.874,-13.851 3.853,-13.852 3.832,-13.853 3.813,-13.854 3.793,-13.855 3.774,-13.856 3.755,-13.857 3.735,-13.858 3.716,-13.859 3.696,-13.86 3.677,-13.861 3.657,-13.862 3.638,-13.863 3.62,-13.864 3.602,-13.865 3.584,-13.865 3.566,-13.866 3.548,-13.867 3.531,-13.868 3.513,-13.869 3.495,-13.87 3.477,-13.87 3.459,-13.871 3.441,-13.872 3.425,-13.873 3.409,-13.874 3.392,-13.874 3.376,-13.875 3.36,-13.876 3.343,-13.876 3.327,-13.877 3.311,-13.878 3.295,-13.879 3.278,-13.879 3.262,-13.88 3.246,-13.881 3.231,-13.881 3.216,-13.882 3.202,-13.883 3.187,-13.883 3.172,-13.884 3.156,-13.884 2.877,-13.896 2.525,-13.908 2.171,-13.919 1.816,-13.928 1.456,-13.936 1.095,-13.942 0.733,-13.946 0.369,-13.949 0,-13.95 -0.039,-13.95 -0.315,-13.949 -0.587,-13.948 -0.858,-13.945 -1.128,-13.942 -1.397,-13.937 -1.662,-13.932 -1.926,-13.926 -2.19,-13.919 -2.453,-13.911 -2.712,-13.902 -2.969,-13.892 -3.23,-13.882 -3.273,-13.88 -3.346,-13.876 -3.419,-13.873 -3.492,-13.87 -3.565,-13.866 -3.639,-13.863 -3.713,-13.859 -3.787,-13.855 -3.861,-13.851 -3.934,-13.847 -4.009,-13.843 -4.084,-13.839 -4.159,-13.835 -4.233,-13.83 -4.308,-13.826 -4.383,-13.821 -4.459,-13.816 -4.493,-13.814 -4.601,-13.807 -4.708,-13.8 -4.816,-13.793 -4.923,-13.785 -5.03,-13.777 -5.137,-13.769 -5.243,-13.761 -5.35,-13.753 -5.456,-13.744 -5.562,-13.735 -5.668,-13.726 -5.773,-13.717 -5.879,-13.707 -5.984,-13.698 -6.089,-13.688 -6.194,-13.678 -6.299,-13.667 -6.403,-13.657 -6.508,-13.646 -6.612,-13.635 -6.716,-13.624 -6.82,-13.613 -6.923,-13.601 -7.026,-13.589 -7.13,-13.577 -7.232,-13.565 -7.342,-13.552 -7.45,-13.538 -7.559,-13.524 -7.667,-13.51 -7.776,-13.496 -7.884,-13.481 -7.991,-13.466 -8.099,-13.451 -8.206,-13.436 -8.313,-13.42 -8.42,-13.404 -8.526,-13.388 -8.632,-13.372 -8.738,-13.355 -8.844,-13.338 -8.95,-13.321 -9.055,-13.303 -9.16,-13.285 -9.264,-13.267 -9.369,-13.249 -9.473,-13.23 -9.577,-13.211 -9.681,-13.192 -9.784,-13.172 -9.887,-13.153 -9.99,-13.133 -10.093,-13.112 -10.195,-13.092 -10.297,-13.071 -10.399,-13.049 -10.5,-13.028 -10.602,-13.006 -10.703,-12.984 -10.809,-12.96 -10.832,-12.955 -10.946,-12.929 -11.059,-12.903 -11.172,-12.876 -11.284,-12.849 -11.396,-12.822 -11.508,-12.794 -11.62,-12.766 -11.731,-12.737 -11.841,-12.708 -11.951,-12.679 -12.061,-12.649 -12.171,-12.619 -12.28,-12.588 -12.389,-12.557 -12.497,-12.525 -12.605,-12.493 -12.713,-12.461 -12.82,-12.428 -12.926,-12.395 -13.033,-12.362 -13.139,-12.328 -13.244,-12.293 -13.349,-12.258 -13.454,-12.223 -13.558,-12.187 -13.662,-12.151 -13.766,-12.114 -13.869,-12.077 -13.972,-12.04 -14.074,-12.002 -14.176,-11.963 -14.277,-11.924 -14.378,-11.885 -14.479,-11.845 -14.579,-11.805 -14.678,-11.764 -14.778,-11.723 -14.876,-11.682 -14.975,-11.64 -15.073,-11.597 -15.17,-11.554 -15.267,-11.511 -15.364,-11.467 -15.46,-11.422 -15.556,-11.377 -15.651,-11.332 -15.746,-11.286 -15.859,-11.23 -15.971,-11.174 -16.083,-11.117 -16.194,-11.059 -16.304,-11.001 -16.414,-10.941 -16.523,-10.881 -16.632,-10.821 -16.739,-10.759 -16.846,-10.697 -16.953,-10.635 -17.058,-10.571 -17.163,-10.507 -17.285,-10.431 -17.405,-10.354 -17.525,-10.276 -17.643,-10.197 -17.761,-10.117 -17.877,-10.036 -18.01,-9.942 -18.14,-9.846 -18.27,-9.75 -18.398,-9.651 -18.54,-9.539 -18.681,-9.426 -18.835,-9.297 -19.003,-9.153 -19.168,-9.006 cw(c-10.612,0.439) -19.359,-8.829 cw(c-10.703,0.342) -19.561,-8.635 cw(c-10.796,0.248) -19.814,-8.377 cw(c-10.964,0.092) -21.027,-6.892 cw(c-10.887,0.145) -21.3,-6.482 cw(c-10.777,0.214) -21.485,-6.183 cw(c-10.666,0.281) -21.631,-5.931 cw(c-10.552,0.346) -21.753,-5.71 cw(c-10.435,0.409) -21.862,-5.505 -21.958,-5.316 -22.042,-5.144 -22.124,-4.969 -22.195,-4.812 -22.265,-4.653 -22.333,-4.493 -22.391,-4.351 -22.447,-4.207 -22.503,-4.063 -22.557,-3.917 -22.61,-3.77 -22.654,-3.643 -22.697,-3.514 -22.74,-3.385 -22.781,-3.255 -22.821,-3.123 -22.86,-2.991 -22.899,-2.858 -22.936,-2.723 -22.967,-2.611 -22.996,-2.497 -23.025,-2.383 -23.054,-2.268 -23.081,-2.153 -23.108,-2.036 -23.134,-1.919 -23.16,-1.801 -23.184,-1.683 -23.209,-1.564 -23.232,-1.444 -23.255,-1.323 -23.276,-1.202 -23.298,-1.079 -23.318,-0.956 -23.338,-0.833 -23.357,-0.708 -23.375,-0.583 -23.393,-0.457 -23.41,-0.331 -23.423,-0.229 -23.435,-0.127 -23.447,-0.024 -23.459,0.079 -23.47,0.183 -23.48,0.288 -23.49,0.392 -23.5,0.498 -23.509,0.603 -23.518,0.71 -23.526,0.816 -23.534,0.923 -23.541,1.031 -23.548,1.139 -23.554,1.248 -23.56,1.357 -23.565,1.467 -23.57,1.577 -23.574,1.688 -23.578,1.799 -23.581,1.911 -23.584,2.023 -23.587,2.136 -23.588,2.249 -23.59,2.363 -23.591,2.477

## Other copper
Top Layer:
  pour cut-out: 1.813,-1.872 1.813,1.828 1.713,1.928 -1.887,1.928 -1.887,-1.872
  pour cut-out: 6.713,20.628 6.713,24.328 6.613,24.428 3.013,24.428 3.013,20.628
  pour cut-out: -2.287,20.728 -2.287,24.428 -2.387,24.528 -5.987,24.528 -5.987,20.728
  pour cut-out: -21.275,-7.425 21.888,-7.425 cw(c21.888,-7.937) 22.25,-7.575 22.25,-8.198 cw(c19.71,-8.198) 21.506,-9.994 16.45,-15.05 -16.023,-15.05 cw(c-16.023,-12.51) -17.819,-14.306 -20.506,-11.619 cw(c-18.71,-9.823) -21.25,-9.823 -21.25,-7.5
Bottom Layer:
  pour cut-out: -21.25,-7.425 21.617,-7.425 cw(c21.617,-8.108) 22.1,-7.625 15.619,-14.106 cw(c13.823,-12.31) 13.823,-14.85 -15.948,-14.85 cw(c-15.948,-12.31) -17.744,-14.106 -21.2,-10.65 cw(c-20.778,-10.228) -21.375,-10.228 -21.375,-7.35
Multi-Layer:
  region net VBAT_SYS: -2.958,-13.627 -2.7,-13.637 -2.441,-13.645 -2.178,-13.653 -1.915,-13.66 -1.65,-13.667 -1.385,-13.672 -1.116,-13.676 -0.846,-13.68 -0.575,-13.682 -0.304,-13.684 -0.028,-13.684 0.012,-13.684 0.38,-13.683 0.744,-13.681 1.107,-13.677 1.468,-13.671 1.828,-13.663 2.183,-13.654 2.536,-13.643 2.888,-13.63 3.168,-13.619 3.19,-13.116 3.252,-11.706 1.208,-12.407 2.96,-8.132 -2.229,-8.132 ccw(c-2.229,-9.137) -2.292,-8.134 ccw(c-2.23,-9.123) -2.516,-8.174 ccw(c-2.229,-9.126) -2.688,-8.244 ccw(c-2.221,-9.141) -3.026,-8.529 ccw(c-2.226,-9.138) -3.118,-8.674 ccw(c-2.238,-9.132) -3.211,-8.941 ccw(c-2.236,-9.132) -3.228,-9.068 ccw(c-2.225,-9.132) -3.23,-9.132 -3.23,-13.617 -3.218,-13.616
  region net EXTGND: 4.856,-13.526 4.975,-13.517 5.088,-13.509 5.201,-13.5 5.314,-13.492 5.427,-13.483 5.539,-13.473 5.651,-13.464 5.763,-13.454 5.875,-13.444 5.986,-13.434 6.098,-13.423 6.209,-13.413 6.319,-13.402 6.43,-13.39 6.54,-13.379 6.651,-13.367 6.761,-13.355 6.87,-13.343 6.98,-13.331 7.089,-13.318 7.198,-13.305 7.307,-13.292 7.415,-13.278 7.524,-13.265 7.632,-13.251 7.74,-13.236 7.847,-13.222 7.955,-13.207 8.062,-13.192 8.169,-13.177 8.275,-13.161 8.382,-13.146 8.488,-13.13 8.594,-13.113 8.7,-13.097 8.805,-13.08 8.91,-13.063 9.015,-13.045 9.12,-13.028 9.224,-13.01 9.329,-12.991 9.432,-12.973 9.536,-12.954 9.64,-12.935 9.743,-12.916 9.846,-12.896 9.948,-12.876 10.051,-12.856 10.153,-12.836 10.254,-12.815 10.356,-12.794 10.457,-12.772 10.558,-12.751 10.659,-12.729 10.76,-12.707 10.81,-12.695 10.81,-9.132 ccw(c9.805,-9.132) 10.808,-9.069 10.808,-9.068 ccw(c9.816,-9.132) 10.79,-8.936 ccw(c9.817,-9.132) 10.699,-8.676 ccw(c9.805,-9.138) 10.608,-8.531 ccw(c9.801,-9.14) 10.279,-8.25 ccw(c9.809,-9.127) 10.135,-8.187 ccw(c9.811,-9.122) 9.853,-8.133 ccw(c9.81,-9.136) 9.81,-8.132 4.992,-8.132 4.634,-9.636 6.184,-9.249
  region net RX_EXT: -9.055,-13.039 -8.95,-13.056 -8.844,-13.073 -8.738,-13.09 -8.632,-13.107 -8.526,-13.123 -8.42,-13.14 -8.313,-13.156 -8.206,-13.171 -8.099,-13.187 -7.991,-13.202 -7.884,-13.217 -7.776,-13.231 -7.667,-13.246 -7.559,-13.26 -7.45,-13.273 -7.342,-13.287 -7.232,-13.3 -7.13,-13.313 -7.026,-13.325 -6.923,-13.336 -6.82,-13.348 -6.716,-13.359 -6.612,-13.371 -6.508,-13.382 -6.403,-13.392 -6.299,-13.403 -6.194,-13.413 -6.089,-13.423 -5.984,-13.433 -5.879,-13.443 -5.773,-13.452 -5.668,-13.461 -5.562,-13.471 -5.456,-13.479 -5.35,-13.488 -5.243,-13.496 -5.137,-13.505 -5.03,-13.513 -4.923,-13.52 -4.816,-13.528 -4.708,-13.535 -4.601,-13.543 -4.493,-13.55 -4.459,-13.552 -4.459,-9.132 ccw(c-5.464,-9.132) -4.461,-9.069 -4.461,-9.068 ccw(c-5.453,-9.132) -4.478,-8.938 ccw(c-5.452,-9.132) -4.57,-8.676 ccw(c-5.463,-9.137) -4.66,-8.533 ccw(c-5.468,-9.141) -4.997,-8.246 ccw(c-5.46,-9.126) -5.153,-8.18 ccw(c-5.458,-9.122) -5.407,-8.133 ccw(c-5.459,-9.136) -5.459,-8.132 -9.81,-8.132 ccw(c-9.81,-9.136) -9.873,-8.134 ccw(c-9.81,-9.124) -10.012,-8.153 ccw(c-9.81,-9.124) -10.259,-8.239 ccw(c-9.805,-9.135) -10.396,-8.323 ccw(c-9.801,-9.14) -10.705,-8.689 ccw(c-9.818,-9.132) -10.81,-9.127 -10.81,-9.132 -10.809,-12.178 -10.809,-12.695 -10.703,-12.719 -10.602,-12.741 -10.5,-12.763 -10.399,-12.785 -10.297,-12.806 -10.195,-12.827 -10.093,-12.848 -9.99,-12.868 -9.887,-12.888 -9.784,-12.908 -9.681,-12.927 -9.577,-12.947 -9.473,-12.966 -9.369,-12.984 -9.264,-13.003 -9.16,-13.021

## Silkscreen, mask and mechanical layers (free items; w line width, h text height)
Top Overlay:
  text "D" at 7.613,16.328 h0.75
  text "C" at 10.813,16.328 h0.75
  text "GND" at 5.25,-7.7 h2.5
  text "+5V" at -2.35,-7.725 h2.5
  text "TXT" at -9.6,-7.75 h2.5
Bottom Overlay:
  circle w0.1: c-3.387,16.828 r0.41
  text "PVT1D - 03/17" at 4.775,21.8 h1.8
  text "TX" at -10.687,17.028 h1.5
  text "R" at -3.212,16.578 h0.8
  text "D" at 7.213,15.528 h1.5
  text "R" at 9.813,15.528 h1.5
  text "C" at 12.413,15.528 h1.5
  text "G" at -11.187,14.528 h1.5
  text "Chibitronics / Chibiscope" at 4.225,8.55 h2
  text "Copyright 2017 Chibitronics PTE LTD" at 10.988,3.928 h1.5
  text "Copyrights: CERN OHL v2.1" at 8.5,2.325 h1.5
  text "Input limited to  / 3.3V max!" at -1.675,-5.4 h2
  text "TXT" at -5.7,-7.75 h2.5
  text "+5V" at 1.3,-7.75 h2.5
  text "GND" at 9.725,-7.75 h2.5
Mechanical 3:
  drawing of 10453 lines, arcs and shapes, not listed
  text "Layer" at 32.177,24.666 h1.52
  text "Name" at 42.589,24.666 h1.52
  text "Material" at 66.204,24.666 h1.52
  text "Thickness" at 88.043,24.666 h1.52
  text "Constant" at 104.548,24.666 h1.52
  text "Board Layer Stack" at 119.023,24.666 h1.52
  text "Silkscreen - top - Pantone 431C - gloss dark gray" at 147.413,21.728 h2.5
  text "1" at 32.177,21.618 h1.52
  text "Top Overlay" at 42.589,21.618 h1.52
  text "2" at 32.177,18.57 h1.52
  text "Top Solder" at 42.589,18.57 h1.52
  text "Solder Resist" at 66.204,18.57 h1.52
  text "0.010mm" at 88.043,18.57 h1.52
  text "3.5" at 104.548,18.57 h1.52
  text "Soldermask - top - 636U - matte teal" at 147.513,18.328 h2.5
  text "3" at 32.177,15.522 h1.52
  text "Top Layer" at 42.589,15.522 h1.52
  text "Copper" at 66.204,15.522 h1.52
  text "0.036mm" at 88.043,15.522 h1.52
  text "4" at 32.177,12.474 h1.52
  text "Dielectric 1" at 42.589,12.474 h1.52
  text "FR-4" at 66.204,12.474 h1.52
  text "1.500mm" at 88.043,12.474 h1.52
  text "4.8" at 104.548,12.474 h1.52
  text "5" at 32.177,9.426 h1.52
  text "Bottom Layer" at 42.589,9.426 h1.52
  text "Copper" at 66.204,9.426 h1.52
  text "0.036mm" at 88.043,9.426 h1.52
  text "6" at 32.177,6.378 h1.52
  text "Bottom Solder" at 42.589,6.378 h1.52
  text "Solder Resist" at 66.204,6.378 h1.52
  text "0.010mm" at 88.043,6.378 h1.52
  text "3.5" at 104.548,6.378 h1.52
  text "Soldermask - bottom - 636U - matte teal" at 147.313,6.328 h2.5
  text "7" at 32.177,3.33 h1.52
  text "Bottom Overlay" at 42.589,3.33 h1.52
  text "Silkscreen - bottom - Pantone 431C - gloss dark gray" at 147.313,3.128 h2.5
  text "Finish: immersion gold" at 32.413,-1.272 h1.5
